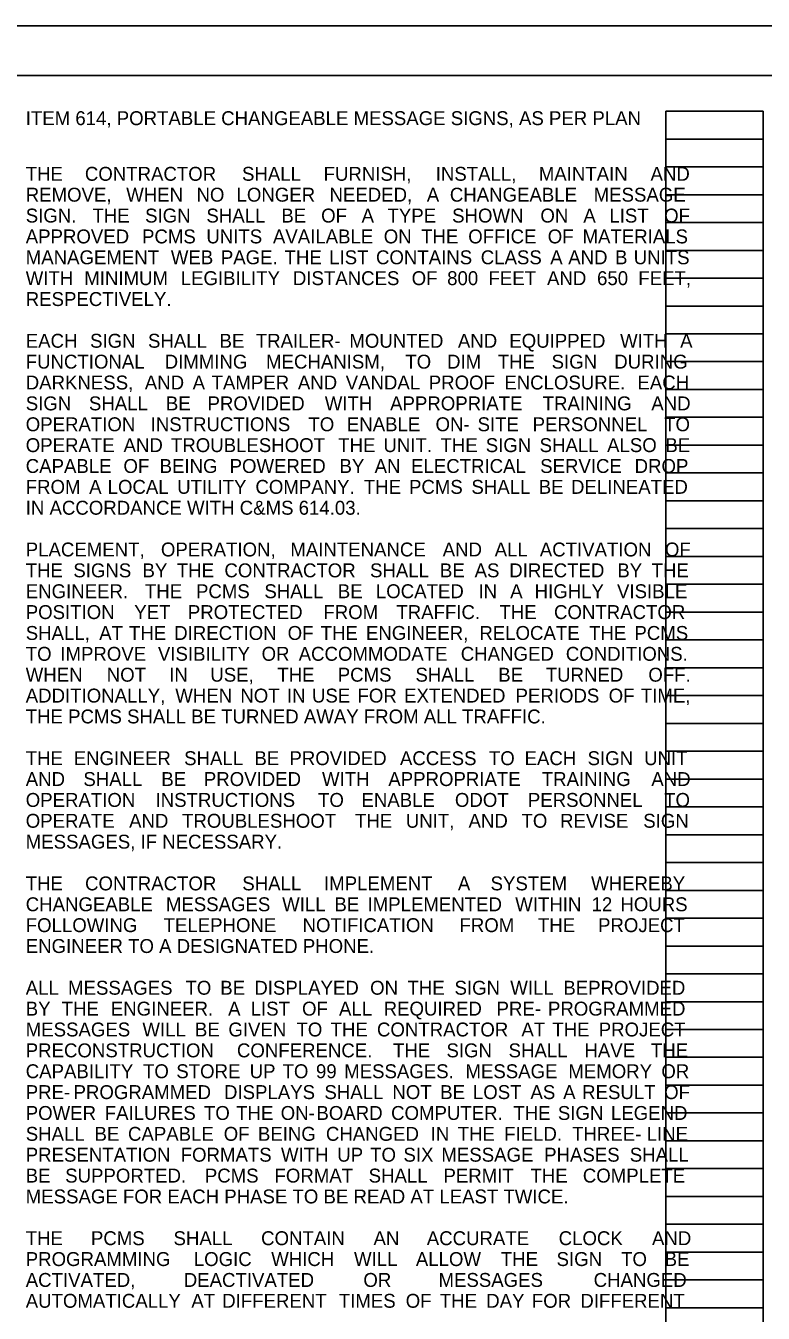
# Model space of a CAD drawing. Extents: x 0 to 34, y 0 to 22.
# Drawn here: x 17.24 to 24.66, y 9.04 to 22 of the extents above; entities that cross this region are included whole.
import ezdxf

# ---------------------------------------------------------------- set-up
doc = ezdxf.new("R2010")
doc.units = 0
for name, color, linetype in [('SH_Border', 7, 'Continuous'), ('SH_Cut_Line', 7, 'Continuous'), ('SH_Data', 7, 'Continuous'), ('SH_Text', 7, 'Continuous')]:
    doc.layers.add(name, color=color, linetype=linetype)

msp = doc.modelspace()

# ---------------------------------------------------------------- linework, layer by layer
at = {"layer": 'SH_Border'}
msp.add_lwpolyline([(1.5, 21.5), (33.5, 21.5), (33.5, 0.5), (1.5, 0.5)], close=True, dxfattribs=at)
at = {"layer": 'SH_Cut_Line'}
msp.add_lwpolyline([(0, 0), (34, 0), (34, 22), (0, 22)], close=True, dxfattribs=at)
at = {"layer": 'SH_Data'}
for p, q in [((23.68, 0.98), (23.68, 21.14)), ((23.68, 21.14), (24.66, 21.14)), ((24.66, 0.98), (24.66, 21.14)), ((23.68, 20.86), (24.66, 20.86)), ((23.68, 20.58), (24.66, 20.58)), ((23.68, 20.3), (24.66, 20.3)), ((23.68, 20.02), (24.66, 20.02)), ((23.68, 19.74), (24.66, 19.74)), ((23.68, 19.46), (24.66, 19.46)), ((23.68, 19.18), (24.66, 19.18)), ((23.68, 18.9), (24.66, 18.9)), ((23.68, 18.62), (24.66, 18.62)), ((23.68, 18.34), (24.66, 18.34)), ((23.68, 18.06), (24.66, 18.06)), ((23.68, 17.78), (24.66, 17.78)), ((23.68, 17.5), (24.66, 17.5)), ((23.68, 17.22), (24.66, 17.22)), ((23.68, 16.94), (24.66, 16.94)), ((23.68, 16.66), (24.66, 16.66)), ((23.68, 16.38), (24.66, 16.38)), ((23.68, 16.1), (24.66, 16.1)), ((23.68, 15.82), (24.66, 15.82)), ((23.68, 15.54), (24.66, 15.54)), ((23.68, 15.26), (24.66, 15.26)), ((23.68, 14.98), (24.66, 14.98)), ((23.68, 14.7), (24.66, 14.7)), ((23.68, 14.42), (24.66, 14.42)), ((23.68, 14.14), (24.66, 14.14)), ((23.68, 13.86), (24.66, 13.86)), ((23.68, 13.58), (24.66, 13.58)), ((23.68, 13.3), (24.66, 13.3)), ((23.68, 13.02), (24.66, 13.02)), ((23.68, 12.74), (24.66, 12.74)), ((23.68, 12.46), (24.66, 12.46)), ((23.68, 12.18), (24.66, 12.18)), ((23.68, 11.9), (24.66, 11.9)), ((23.68, 11.62), (24.66, 11.62)), ((23.68, 11.34), (24.66, 11.34)), ((23.68, 11.06), (24.66, 11.06)), ((23.68, 10.78), (24.66, 10.78)), ((23.68, 10.5), (24.66, 10.5)), ((23.68, 10.22), (24.66, 10.22)), ((23.68, 9.94), (24.66, 9.94)), ((23.68, 9.66), (24.66, 9.66)), ((23.68, 9.38), (24.66, 9.38)), ((23.68, 9.1), (24.66, 9.1))]:
    msp.add_line(p, q, dxfattribs=at)

# ---------------------------------------------------------------- texts
at = {"layer": 'SH_Text'}
for s, p in [('ITEM 614, PORTABLE CHANGEABLE MESSAGE SIGNS, AS PER PLAN', (17.24, 21)), ('THE ', (17.24, 20.44)), ('CONTRACTOR ', (17.835, 20.44)), ('SHALL ', (19.416, 20.44)), ('FURNISH, ', (20.237, 20.44)), ('INSTALL, ', (21.365, 20.44)), ('MAINTAIN ', (22.402, 20.44)), ('AND ', (23.526, 20.44)), ('REMOVE, ', (17.24, 20.23)), ('WHEN ', (18.251, 20.23)), ('NO ', (18.958, 20.23)), ('LONGER ', (19.361, 20.23)), ('NEEDED, ', (20.296, 20.23)), ('A ', (21.275, 20.23)), ('CHANGEABLE ', (21.507, 20.23)), ('MESSAGE ', (22.954, 20.23)), ('SIGN. ', (17.24, 20.02)), ('THE ', (17.911, 20.02)), ('SIGN ', (18.441, 20.02)), ('SHALL ', (19.058, 20.02)), ('BE ', (19.812, 20.02)), ('OF ', (20.212, 20.02)), ('A ', (20.619, 20.02)), ('TYPE ', (20.88, 20.02)), ('SHOWN ', (21.53, 20.02)), ('ON ', (22.418, 20.02)), ('A ', (22.85, 20.02)), ('LIST ', (23.112, 20.02)), ('OF ', (23.663, 20.02)), ('APPROVED ', (17.24, 19.81)), ('PCMS ', (18.41, 19.81)), ('UNITS ', (19.057, 19.81)), ('ON ', (20.842, 19.81)), ('OFFICE ', (21.692, 19.81)), ('OF ', (22.492, 19.81)), ('MATERIALS ', (22.842, 19.81)), ('AVAILABLE ', (19.727, 19.81)), ('THE ', (21.218, 19.81)), ('MANAGEMENT ', (17.24, 19.6)), ('WEB ', (18.7, 19.6)), ('PAGE. ', (19.203, 19.6)), ('THE ', (19.844, 19.6)), ('LIST ', (20.293, 19.6)), ('CONTAINS ', (20.764, 19.6)), ('CLASS ', (21.818, 19.6)), ('A ', (22.517, 19.6)), ('AND ', (22.698, 19.6)), ('B ', (23.169, 19.6)), ('UNITS ', (23.357, 19.6)), ('WITH ', (17.24, 19.39)), ('MINIMUM ', (17.829, 19.39)), ('LEGIBILITY ', (18.799, 19.39)), ('DISTANCES ', (19.928, 19.39)), ('OF ', (21.123, 19.39)), ('800 ', (21.48, 19.39)), ('FEET ', (21.896, 19.39)), ('AND ', (22.485, 19.39)), ('650 ', (22.988, 19.39)), ('FEET, ', (23.403, 19.39)), ('RESPECTIVELY.', (17.24, 19.18)), ('EACH ', (17.24, 18.76)), ('SIGN ', (17.887, 18.76)), ('SHALL ', (18.47, 18.76)), ('BE ', (19.19, 18.76)), ('TRAILER-', (19.555, 18.76)), ('MOUNTED ', (20.496, 18.76)), ('AND ', (21.588, 18.76)), ('EQUIPPED ', (22.105, 18.76)), ('WITH ', (23.22, 18.76)), ('A ', (23.824, 18.76)), ('FUNCTIONAL ', (17.24, 18.55)), ('DIMMING ', (18.638, 18.55)), ('MECHANISM, ', (19.658, 18.55)), ('TO ', (21.059, 18.55)), ('DIM ', (21.479, 18.55)), ('THE ', (21.989, 18.55)), ('SIGN ', (22.531, 18.55)), ('DURING ', (23.161, 18.55)), ('DARKNESS, ', (17.24, 18.34)), ('AND ', (18.438, 18.34)), ('A ', (18.919, 18.34)), ('TAMPER ', (19.11, 18.34)), ('AND ', (19.978, 18.34)), ('VANDAL ', (20.459, 18.34)), ('PROOF ', (21.295, 18.34)), ('ENCLOSURE. ', (22.055, 18.34)), ('EACH ', (23.394, 18.34)), ('SIGN ', (17.24, 18.13)), ('SHALL ', (17.876, 18.13)), ('BE ', (18.65, 18.13)), ('PROVIDED ', (19.069, 18.13)), ('WITH ', (20.249, 18.13)), ('APPROPRIATE ', (20.906, 18.13)), ('TRAINING ', (22.441, 18.13)), ('AND ', (23.534, 18.13)), ('OPERATION ', (17.24, 17.92)), ('INSTRUCTIONS ', (18.497, 17.92)), ('TO ', (20.084, 17.92)), ('ENABLE ', (20.471, 17.92)), ('ON-', (21.363, 17.92)), ('SITE ', (21.786, 17.92)), ('PERSONNEL ', (22.34, 17.92)), ('TO ', (23.663, 17.92)), ('OPERATE ', (17.24, 17.71)), ('AND ', (18.224, 17.71)), ('TROUBLESHOOT ', (18.701, 17.71)), ('THE ', (20.384, 17.71)), ('UNIT. ', (20.839, 17.71)), ('THE ', (21.413, 17.71)), ('SIGN ', (21.868, 17.71)), ('SHALL ', (22.41, 17.71)), ('ALSO ', (23.089, 17.71)), ('BE ', (23.675, 17.71)), ('CAPABLE ', (17.24, 17.5)), ('OF ', (18.223, 17.5)), ('BEING ', (18.587, 17.5)), ('POWERED ', (19.291, 17.5)), ('BY ', (20.397, 17.5)), ('AN ', (20.75, 17.5)), ('ELECTRICAL ', (21.117, 17.5)), ('SERVICE ', (22.416, 17.5)), ('DROP ', (23.366, 17.5)), ('FROM ', (17.24, 17.29)), ('A ', (17.878, 17.29)), ('LOCAL ', (18.064, 17.29)), ('UTILITY ', (18.764, 17.29)), ('COMPANY. ', (19.551, 17.29)), ('THE ', (20.642, 17.29)), ('PCMS ', (21.096, 17.29)), ('SHALL ', (21.724, 17.29)), ('BE ', (22.402, 17.29)), ('DELINEATED ', (22.726, 17.29)), ('IN ACCORDANCE WITH C&MS 614.03.', (17.24, 17.08)), ('PLACEMENT, ', (17.24, 16.66)), ('OPERATION, ', (18.6, 16.66)), ('MAINTENANCE ', (19.902, 16.66)), ('AND ', (21.435, 16.66)), ('ALL ', (21.958, 16.66)), ('ACTIVATION ', (22.412, 16.66)), ('OF ', (23.671, 16.66)), ('THE ', (17.24, 16.45)), ('SIGNS ', (17.719, 16.45)), ('BY ', (18.415, 16.45)), ('THE ', (18.76, 16.45)), ('CONTRACTOR ', (19.239, 16.45)), ('SHALL ', (20.704, 16.45)), ('BE ', (21.407, 16.45)), ('AS ', (21.756, 16.45)), ('DIRECTED ', (22.105, 16.45)), ('BY ', (23.192, 16.45)), ('THE ', (23.537, 16.45)), ('ENGINEER. ', (17.24, 16.24)), ('THE ', (18.439, 16.24)), ('PCMS ', (18.953, 16.24)), ('SHALL ', (19.641, 16.24)), ('BE ', (20.38, 16.24)), ('LOCATED ', (20.763, 16.24)), ('IN ', (21.795, 16.24)), ('A ', (22.114, 16.24)), ('HIGHLY ', (22.36, 16.24)), ('VISIBLE ', (23.189, 16.24)), ('POSITION ', (17.24, 16.03)), ('YET ', (18.332, 16.03)), ('PROTECTED ', (18.871, 16.03)), ('FROM ', (20.235, 16.03)), ('TRAFFIC. ', (20.969, 16.03)), ('THE ', (22.006, 16.03)), ('CONTRACTOR ', (22.555, 16.03)), ('SHALL, ', (17.24, 15.82)), ('AT ', (17.979, 15.82)), ('THE ', (18.279, 15.82)), ('DIRECTION ', (18.734, 15.82)), ('OF ', (19.875, 15.82)), ('THE ', (20.207, 15.82)), ('ENGINEER, ', (20.663, 15.82)), ('RELOCATE ', (21.804, 15.82)), ('THE ', (22.908, 15.82)), ('PCMS ', (23.364, 15.82)), ('TO ', (17.24, 15.61)), ('IMPROVE ', (17.588, 15.61)), ('VISIBILITY ', (18.57, 15.61)), ('OR ', (19.613, 15.61)), ('ACCOMMODATE ', (19.986, 15.61)), ('CHANGED ', (21.617, 15.61)), ('CONDITIONS. ', (22.674, 15.61)), ('WHEN ', (17.24, 15.4)), ('NOT ', (18.055, 15.4)), ('IN ', (18.684, 15.4)), ('USE, ', (19.097, 15.4)), ('THE ', (19.771, 15.4)), ('PCMS ', (20.379, 15.4)), ('SHALL ', (21.161, 15.4)), ('BE ', (21.994, 15.4)), ('TURNED ', (22.472, 15.4)), ('OFF. ', (23.504, 15.4)), ('ADDITIONALLY, ', (17.24, 15.19)), ('WHEN ', (18.745, 15.19)), ('NOT ', (19.399, 15.19)), ('IN ', (19.868, 15.19)), ('USE ', (20.12, 15.19)), ('FOR ', (20.578, 15.19)), ('EXTENDED ', (21.047, 15.19)), ('PERIODS ', (22.168, 15.19)), ('OF ', (23.105, 15.19)), ('TIME, ', (23.429, 15.19)), ('THE PCMS SHALL BE TURNED AWAY FROM ALL TRAFFIC.', (17.24, 14.98)), ('THE ', (17.24, 14.56)), ('ENGINEER ', (17.722, 14.56)), ('SHALL ', (18.834, 14.56)), ('BE ', (19.541, 14.56)), ('PROVIDED ', (19.893, 14.56)), ('ACCESS ', (21.005, 14.56)), ('TO ', (21.9, 14.56)), ('EACH ', (22.259, 14.56)), ('SIGN ', (22.893, 14.56)), ('UNIT ', (23.462, 14.56)), ('AND ', (17.24, 14.35)), ('SHALL ', (17.82, 14.35)), ('BE ', (18.604, 14.35)), ('PROVIDED ', (19.032, 14.35)), ('WITH ', (20.221, 14.35)), ('APPROPRIATE ', (20.888, 14.35)), ('TRAINING ', (22.432, 14.35)), ('AND ', (23.534, 14.35)), ('OPERATION ', (17.24, 14.14)), ('INSTRUCTIONS ', (18.546, 14.14)), ('TO ', (20.181, 14.14)), ('ENABLE ', (20.618, 14.14)), ('ODOT ', (21.558, 14.14)), ('PERSONNEL ', (22.292, 14.14)), ('TO ', (23.663, 14.14)), ('OPERATE ', (17.24, 13.93)), ('AND ', (18.28, 13.93)), ('TROUBLESHOOT ', (18.813, 13.93)), ('THE ', (20.553, 13.93)), ('UNIT, ', (21.064, 13.93)), ('AND ', (21.695, 13.93)), ('TO ', (22.228, 13.93)), ('REVISE ', (22.616, 13.93)), ('SIGN ', (23.453, 13.93)), ('MESSAGES, IF NECESSARY.', (17.24, 13.72)), ('THE ', (17.24, 13.3)), ('CONTRACTOR ', (17.837, 13.3)), ('SHALL ', (19.419, 13.3)), ('IMPLEMENT ', (20.241, 13.3)), ('A ', (21.588, 13.3)), ('SYSTEM ', (21.917, 13.3)), ('WHEREBY ', (22.928, 13.3)), ('CHANGEABLE ', (17.24, 13.09)), ('MESSAGES ', (18.65, 13.09)), ('WILL ', (19.82, 13.09)), ('BE ', (20.346, 13.09)), ('IMPLEMENTED ', (20.679, 13.09)), ('WITHIN ', (22.165, 13.09)), ('12 ', (22.933, 13.09)), ('HOURS ', (23.223, 13.09)), ('FOLLOWING ', (17.24, 12.88)), ('TELEPHONE ', (18.627, 12.88)), ('NOTIFICATION ', (20.025, 12.88)), ('FROM ', (21.604, 12.88)), ('THE ', (22.393, 12.88)), ('PROJECT ', (22.998, 12.88)), ('ENGINEER TO A DESIGNATED PHONE.', (17.24, 12.67)), ('ALL ', (17.24, 12.25)), ('MESSAGES ', (17.666, 12.25)), ('TO ', (18.847, 12.25)), ('BE ', (19.197, 12.25)), ('DISPLAYED ', (19.54, 12.25)), ('ON ', (20.705, 12.25)), ('THE ', (21.081, 12.25)), ('SIGN ', (21.554, 12.25)), ('WILL ', (22.115, 12.25)), ('BEPROVIDED ', (22.649, 12.25)), ('BY ', (17.24, 12.04)), ('THE ', (17.601, 12.04)), ('ENGINEER. ', (18.096, 12.04)), ('A ', (19.276, 12.04)), ('LIST ', (19.503, 12.04)), ('OF ', (20.02, 12.04)), ('ALL ', (20.392, 12.04)), ('REQUIRED ', (20.841, 12.04)), ('PRE-', (21.977, 12.04)), ('PROGRAMMED ', (22.494, 12.04)), ('MESSAGES ', (17.24, 11.83)), ('WILL ', (18.414, 11.83)), ('BE ', (18.942, 11.83)), ('GIVEN ', (19.279, 11.83)), ('TO ', (19.964, 11.83)), ('THE ', (20.307, 11.83)), ('CONTRACTOR ', (20.774, 11.83)), ('AT ', (22.227, 11.83)), ('THE ', (22.538, 11.83)), ('PROJECT ', (23.005, 11.83)), ('PRECONSTRUCTION ', (17.24, 11.62)), ('CONFERENCE. ', (19.365, 11.62)), ('THE ', (20.935, 11.62)), ('SIGN ', (21.473, 11.62)), ('SHALL ', (22.098, 11.62)), ('HAVE ', (22.861, 11.62)), ('THE ', (23.53, 11.62)), ('CAPABILITY ', (17.24, 11.41)), ('TO ', (18.42, 11.41)), ('STORE ', (18.755, 11.41)), ('UP ', (19.493, 11.41)), ('TO ', (19.824, 11.41)), ('99 ', (20.16, 11.41)), ('MESSAGES. ', (20.444, 11.41)), ('MESSAGE ', (21.664, 11.41)), ('MEMORY ', (22.699, 11.41)), ('OR ', (23.635, 11.41)), ('PRE-', (17.24, 11.2)), ('PROGRAMMED ', (17.721, 11.2)), ('DISPLAYS ', (19.235, 11.2)), ('SHALL ', (20.245, 11.2)), ('NOT ', (20.929, 11.2)), ('BE ', (21.41, 11.2)), ('LOST ', (21.739, 11.2)), ('AS ', (22.318, 11.2)), ('A ', (22.647, 11.2)), ('RESULT ', (22.838, 11.2)), ('OF ', (23.663, 11.2)), ('POWER ', (17.24, 10.99)), ('FAILURES ', (18.035, 10.99)), ('TO ', (19.033, 10.99)), ('THE ', (19.357, 10.99)), ('ON-', (19.805, 10.99)), ('BOARD ', (20.165, 10.99)), ('COMPUTER. ', (20.916, 10.99)), ('THE ', (22.146, 10.99)), ('SIGN ', (22.594, 10.99)), ('LEGEND ', (23.128, 10.99)), ('SHALL ', (17.24, 10.78)), ('BE ', (17.932, 10.78)), ('CAPABLE ', (18.269, 10.78)), ('OF ', (19.232, 10.78)), ('BEING ', (19.576, 10.78)), ('CHANGED ', (20.26, 10.78)), ('IN ', (21.314, 10.78)), ('THE ', (21.586, 10.78)), ('FIELD. ', (22.053, 10.78)), ('THREE-', (22.737, 10.78)), ('LINE ', (23.487, 10.78)), ('PRESENTATION ', (17.24, 10.57)), ('FORMATS ', (18.799, 10.57)), ('WITH ', (19.808, 10.57)), ('UP ', (20.374, 10.57)), ('TO ', (20.705, 10.57)), ('SIX ', (21.04, 10.57)), ('MESSAGE ', (21.422, 10.57)), ('PHASES ', (22.456, 10.57)), ('SHALL ', (23.317, 10.57)), ('BE ', (17.24, 10.36)), ('SUPPORTED. ', (17.637, 10.36)), ('PCMS ', (19.042, 10.36)), ('FORMAT ', (19.743, 10.36)), ('SHALL ', (20.69, 10.36)), ('PERMIT ', (21.443, 10.36)), ('THE ', (22.318, 10.36)), ('COMPLETE ', (22.845, 10.36)), ('MESSAGE FOR EACH PHASE TO BE READ AT LEAST TWICE.', (17.24, 10.15)), ('THE ', (17.24, 9.73)), ('PCMS ', (17.896, 9.73)), ('SHALL ', (18.727, 9.73)), ('CONTAIN ', (19.608, 9.73)), ('AN ', (20.739, 9.73)), ('ACCURATE ', (21.275, 9.73)), ('CLOCK ', (22.602, 9.73)), ('AND ', (23.541, 9.73)), ('PROGRAMMING ', (17.24, 9.52)), ('LOGIC ', (18.931, 9.52)), ('WHICH ', (19.71, 9.52)), ('WILL ', (20.543, 9.52)), ('ALLOW ', (21.165, 9.52)), ('THE ', (22.02, 9.52)), ('SIGN ', (22.581, 9.52)), ('TO ', (23.23, 9.52)), ('BE ', (23.668, 9.52)), ('ACTIVATED, ', (17.24, 9.31)), ('DEACTIVATED ', (18.83, 9.31)), ('OR ', (20.637, 9.31)), ('MESSAGES ', (21.393, 9.31)), ('CHANGED ', (22.954, 9.31)), ('AUTOMATICALLY ', (17.24, 9.1)), ('AT ', (18.906, 9.1)), ('DIFFERENT ', (19.217, 9.1)), ('TIMES ', (20.39, 9.1)), ('OF ', (21.063, 9.1)), ('THE ', (21.406, 9.1)), ('DAY ', (21.873, 9.1)), ('FOR ', (22.332, 9.1)), ('DIFFERENT ', (22.82, 9.1))]:
    msp.add_text(s, height=0.14, dxfattribs=at).set_placement(p)

doc.saveas('drawing.dxf')
